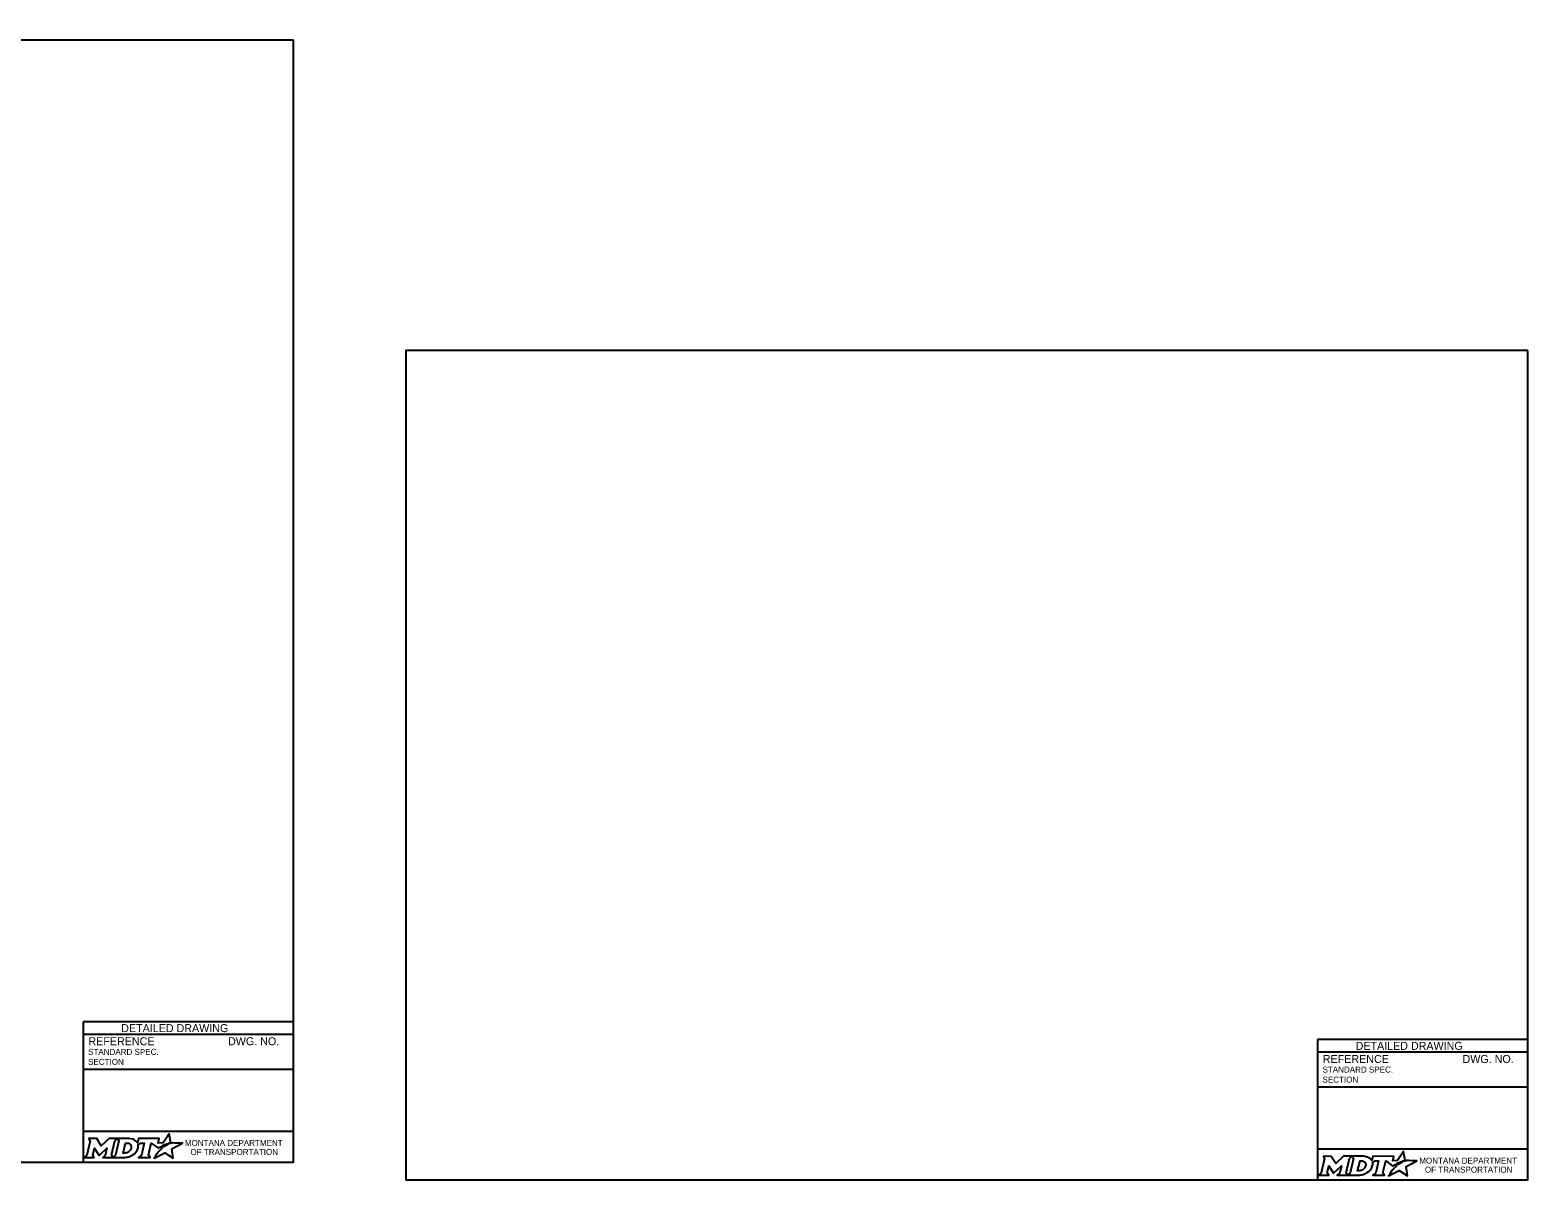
# Model space of a CAD drawing. Extents: x 49991.4 to 50021, y 49987.6 to 50011.4.
# Drawn here: x 50005.99 to 50021.04, y 49999.74 to 50011.36 of the extents above; entities that cross this region are included whole.
import ezdxf

# ---------------------------------------------------------------- set-up
doc = ezdxf.new("R2010")
doc.units = 0
for name, color, linetype in [('Default', 7, 'Continuous'), ('Level 1', 7, 'Continuous'), ('Level 2', 7, 'Continuous'), ('Level 4', 7, 'Continuous')]:
    doc.layers.add(name, color=color, linetype=linetype)

msp = doc.modelspace()

# ---------------------------------------------------------------- linework, layer by layer
at = {"layer": 'Default'}
for points in [[(50018.893, 50000.121), (50018.907, 50000.097), (50018.874, 49999.954), (50018.848, 49999.931), (50018.95, 49999.931), (50018.936, 49999.954), (50018.952, 50000.024), (50018.996, 49999.955), (50019.002, 49999.955), (50019.077, 50000.025), (50019.06, 49999.954), (50019.035, 49999.932), (50019.137, 49999.932), (50019.123, 49999.955), (50019.156, 50000.097)], [(50019.156, 50000.097), (50019.182, 50000.121), (50019.099, 50000.121), (50019.02, 50000.048), (50018.975, 50000.12), (50018.893, 50000.121)], [(50019.295, 50000.121), (50019.182, 50000.121), (50019.196, 50000.098), (50019.163, 49999.954), (50019.137, 49999.932), (50019.248, 49999.932)], [(50019.319, 50000.034), (50019.318, 50000.026), (50019.315, 50000.017), (50019.311, 50000.008), (50019.305, 50000.001), (50019.299, 49999.994), (50019.291, 49999.988), (50019.282, 49999.983), (50019.273, 49999.979), (50019.264, 49999.977), (50019.255, 49999.976), (50019.239, 49999.976), (50019.263, 50000.076), (50019.279, 50000.076), (50019.286, 50000.075), (50019.294, 50000.073), (50019.301, 50000.07), (50019.307, 50000.066), (50019.311, 50000.061), (50019.315, 50000.055), (50019.318, 50000.049), (50019.319, 50000.042), (50019.32, 50000.038), (50019.319, 50000.034)], [(50019.7, 50000.068), (50019.69, 50000.074), (50019.702, 50000.076), (50019.713, 50000.078), (50019.696, 50000.168), (50019.636, 50000.077), (50019.589, 50000.076), (50019.599, 50000.12), (50019.39, 50000.121), (50019.38, 50000.078), (50019.374, 50000.086)], [(50019.387, 50000.062), (50019.411, 50000.075), (50019.448, 50000.075), (50019.42, 49999.954), (50019.392, 49999.931), (50019.508, 49999.931), (50019.491, 49999.954), (50019.52, 50000.075), (50019.591, 50000.023), (50019.612, 50000.038), (50019.632, 50000.027)], [(50019.576, 49999.971), (50019.561, 49999.947), (50019.556, 49999.939), (50019.55, 49999.931), (50019.548, 49999.926), (50019.653, 49999.979), (50019.737, 49999.924), (50019.724, 50000.017), (50019.831, 50000.075), (50019.782, 50000.076), (50019.751, 50000.077), (50019.731, 50000.077), (50019.724, 50000.075), (50019.719, 50000.074), (50019.711, 50000.072), (50019.7, 50000.068)], [(50019.65, 50000.04), (50019.648, 50000.039), (50019.629, 50000.048), (50019.639, 50000.054), (50019.644, 50000.056), (50019.652, 50000.06), (50019.658, 50000.063), (50019.666, 50000.066), (50019.673, 50000.068), (50019.685, 50000.061), (50019.681, 50000.059), (50019.676, 50000.056), (50019.672, 50000.054), (50019.667, 50000.051), (50019.665, 50000.05), (50019.662, 50000.049), (50019.66, 50000.047), (50019.658, 50000.046), (50019.655, 50000.044), (50019.652, 50000.042), (50019.65, 50000.04)], [(50019.293, 49999.939), (50019.302, 49999.942), (50019.315, 49999.947), (50019.335, 49999.958)], [(50019.59, 49999.987), (50019.59, 49999.987)]]:
    msp.add_lwpolyline(points, dxfattribs=at)
for centre, radius, start, end in [((50019.319, 50000.042), 0.0709, 339.5329, 15.8582), ((50019.274, 50000.059), 0.118, 300.9103, 339.1383)]:
    msp.add_arc(centre, radius, start, end, dxfattribs=at)
for centre, major_axis, ratio, start_param, end_param in [((50019.293, 50000.073), (0.0834, -0.0037), 0.568097, 0.61298, 1.570796), ((50019.349, 50000.081), (0.0361, -0.0295), 0.469099, 1.225588, 1.570796), ((50019.621, 50000.017), (-0.0112, -0.0097), 0.021651, 3.157348, 6.283185), ((50019.248, 50000.08), (0, 0.148), 0.987302, 3.139398, 3.456847), ((50019.583, 49999.979), (-0.00694, -0.00806), 0.008222, 0, 3.137361), ((50019.6, 49999.997), (-0.0098, -0.0102), 0.016458, 3.141593, 6.279097)]:
    msp.add_ellipse(centre, major_axis=major_axis, ratio=ratio, start_param=start_param, end_param=end_param, dxfattribs=at)
at = {"layer": 'Level 1'}
for p, q in [((50008.765, 50011.363), (50008.765, 50011.363)), ((50021.038, 50008.524), (50021.038, 50008.524)), ((50009.537, 49999.736), (50009.537, 49999.736))]:
    msp.add_line(p, q, dxfattribs=at)
for points in [[(50008.615, 50011.263), (50000.336, 50011.263), (50000.336, 50000.062), (50008.615, 50000.062)], [(50020.938, 50008.165), (50009.737, 50008.165), (50009.737, 49999.886), (50020.938, 49999.886)]]:
    msp.add_lwpolyline(points, close=True, dxfattribs=at)
at = {"layer": 'Level 2'}
for p, q in [((50008.615, 50001.462), (50006.515, 50001.462)), ((50006.515, 50001.462), (50006.515, 50000.062)), ((50008.615, 50001.337), (50006.515, 50001.337)), ((50008.251, 50001.122), (50008.251, 50001.122)), ((50008.615, 50000.987), (50006.515, 50000.987)), ((50007.009, 50001.063), (50007.009, 50001.063)), ((50007.565, 50000.738), (50007.565, 50000.738)), ((50008.615, 50000.369), (50006.515, 50000.369))]:
    msp.add_line(p, q, dxfattribs=at)
for points in [[(50007.377, 50000.245), (50007.367, 50000.25), (50007.378, 50000.253), (50007.39, 50000.255), (50007.373, 50000.345), (50007.313, 50000.254), (50007.266, 50000.253), (50007.276, 50000.297), (50007.067, 50000.297), (50007.057, 50000.255), (50007.051, 50000.263)], [(50006.57, 50000.297), (50006.584, 50000.274), (50006.551, 50000.131), (50006.525, 50000.108), (50006.627, 50000.108), (50006.613, 50000.131), (50006.629, 50000.201), (50006.673, 50000.132), (50006.678, 50000.132), (50006.753, 50000.202), (50006.737, 50000.13), (50006.712, 50000.108), (50006.814, 50000.108), (50006.8, 50000.132), (50006.833, 50000.274)], [(50006.833, 50000.274), (50006.859, 50000.297), (50006.776, 50000.297), (50006.697, 50000.224), (50006.652, 50000.297), (50006.57, 50000.297)], [(50006.972, 50000.297), (50006.859, 50000.297), (50006.873, 50000.275), (50006.839, 50000.131), (50006.814, 50000.108), (50006.925, 50000.108)], [(50006.996, 50000.211), (50006.995, 50000.203), (50006.992, 50000.193), (50006.988, 50000.185), (50006.982, 50000.178), (50006.976, 50000.171), (50006.968, 50000.164), (50006.959, 50000.16), (50006.95, 50000.156), (50006.941, 50000.154), (50006.932, 50000.153), (50006.916, 50000.153), (50006.94, 50000.253), (50006.956, 50000.253), (50006.963, 50000.252), (50006.971, 50000.25), (50006.977, 50000.247), (50006.983, 50000.243), (50006.988, 50000.238), (50006.992, 50000.232), (50006.995, 50000.226), (50006.996, 50000.218), (50006.996, 50000.215), (50006.996, 50000.211)], [(50007.064, 50000.238), (50007.088, 50000.251), (50007.125, 50000.251), (50007.097, 50000.131), (50007.069, 50000.108), (50007.185, 50000.108), (50007.168, 50000.131), (50007.196, 50000.251), (50007.268, 50000.2), (50007.289, 50000.215), (50007.309, 50000.204)], [(50007.253, 50000.148), (50007.237, 50000.124), (50007.233, 50000.116), (50007.227, 50000.107), (50007.225, 50000.103), (50007.33, 50000.156), (50007.414, 50000.101), (50007.401, 50000.194), (50007.508, 50000.252), (50007.458, 50000.253), (50007.428, 50000.253), (50007.407, 50000.254), (50007.401, 50000.252), (50007.396, 50000.251), (50007.387, 50000.249), (50007.377, 50000.245)], [(50007.327, 50000.217), (50007.324, 50000.215), (50007.306, 50000.225), (50007.316, 50000.231), (50007.32, 50000.233), (50007.329, 50000.237), (50007.335, 50000.239), (50007.343, 50000.243), (50007.35, 50000.245), (50007.362, 50000.238), (50007.358, 50000.236), (50007.353, 50000.233), (50007.349, 50000.231), (50007.344, 50000.228), (50007.342, 50000.227), (50007.339, 50000.225), (50007.337, 50000.224), (50007.334, 50000.222), (50007.332, 50000.221), (50007.329, 50000.219), (50007.327, 50000.217)], [(50006.97, 50000.116), (50006.979, 50000.118), (50006.992, 50000.124), (50007.012, 50000.135)], [(50007.267, 50000.164), (50007.267, 50000.164)]]:
    msp.add_lwpolyline(points, dxfattribs=at)
for centre, radius, start, end in [((50006.951, 50000.236), 0.118, 300.9103, 339.1383), ((50006.995, 50000.219), 0.0709, 339.5329, 15.8582)]:
    msp.add_arc(centre, radius, start, end, dxfattribs=at)
for centre, major_axis, ratio, start_param, end_param in [((50006.97, 50000.25), (0.0834, -0.0037), 0.568097, 0.61298, 1.570796), ((50007.026, 50000.257), (0.0361, -0.0295), 0.469099, 1.225588, 1.570796), ((50007.276, 50000.174), (-0.0098, -0.0102), 0.016458, 3.141593, 6.279097), ((50007.297, 50000.194), (-0.0112, -0.0097), 0.021651, 3.157348, 6.283185), ((50006.925, 50000.257), (0, 0.148), 0.987302, 3.139398, 3.456847), ((50007.26, 50000.156), (-0.00694, -0.00806), 0.008222, 0, 3.137361)]:
    msp.add_ellipse(centre, major_axis=major_axis, ratio=ratio, start_param=start_param, end_param=end_param, dxfattribs=at)
at = {"layer": 'Level 4'}
for p, q in [((50020.938, 50001.286), (50018.838, 50001.286)), ((50018.838, 50001.286), (50018.838, 49999.886)), ((50020.938, 50001.161), (50018.838, 50001.161)), ((50020.574, 50000.946), (50020.574, 50000.946)), ((50020.938, 50000.811), (50018.838, 50000.811)), ((50019.332, 50000.886), (50019.332, 50000.886)), ((50019.888, 50000.562), (50019.888, 50000.562)), ((50020.938, 50000.193), (50018.838, 50000.193))]:
    msp.add_line(p, q, dxfattribs=at)

# ---------------------------------------------------------------- texts
at = {"layer": 'Default'}
for s, p in [('MONTANA DEPARTMENT', (50019.854, 50000.047)), ('OF TRANSPORTATION', (50019.91, 49999.957))]:
    msp.add_text(s, height=0.06, dxfattribs=at).set_placement(p)
at = {"layer": 'Level 2'}
for s, height, p in [('DETAILED DRAWING', 0.0799, (50006.896, 50001.36)), ('REFERENCE', 0.08, (50006.568, 50001.229)), ('DWG. NO.', 0.08, (50007.962, 50001.229)), ('STANDARD SPEC.', 0.06, (50006.565, 50001.133)), ('SECTION', 0.06, (50006.565, 50001.033)), ('MONTANA DEPARTMENT', 0.06, (50007.531, 50000.224)), ('OF TRANSPORTATION', 0.06, (50007.587, 50000.134))]:
    msp.add_text(s, height=height, dxfattribs=at).set_placement(p)
at = {"layer": 'Level 4'}
for s, height, p in [('DETAILED DRAWING', 0.0799, (50019.219, 50001.183)), ('REFERENCE', 0.08, (50018.891, 50001.052)), ('DWG. NO.', 0.08, (50020.286, 50001.052)), ('STANDARD SPEC.', 0.06, (50018.888, 50000.956)), ('SECTION', 0.06, (50018.888, 50000.856))]:
    msp.add_text(s, height=height, dxfattribs=at).set_placement(p)

doc.saveas('drawing.dxf')
